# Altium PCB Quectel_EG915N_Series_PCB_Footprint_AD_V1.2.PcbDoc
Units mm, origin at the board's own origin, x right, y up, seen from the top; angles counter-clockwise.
Board outline 152.4 x 101.6 mm, 2 copper layers (Top Layer, Bottom Layer); 1 components, 0 nets, 126 pads, 0 vias.
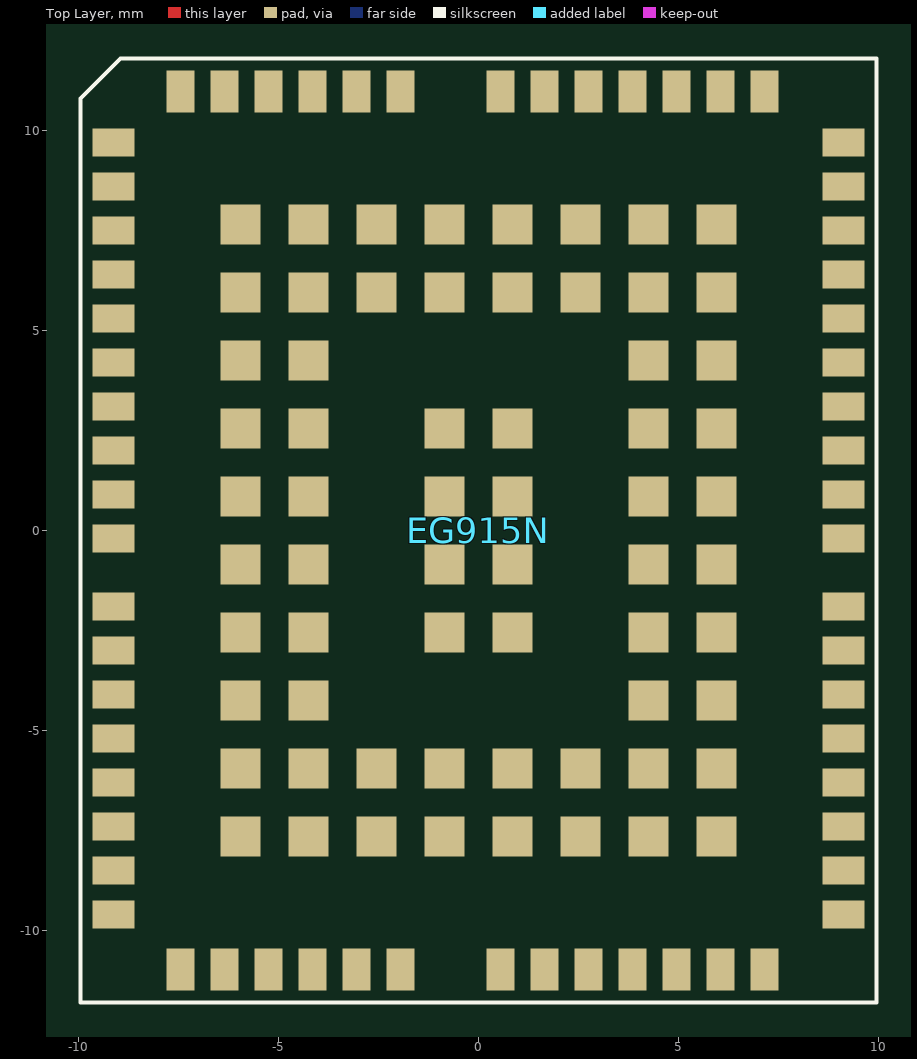
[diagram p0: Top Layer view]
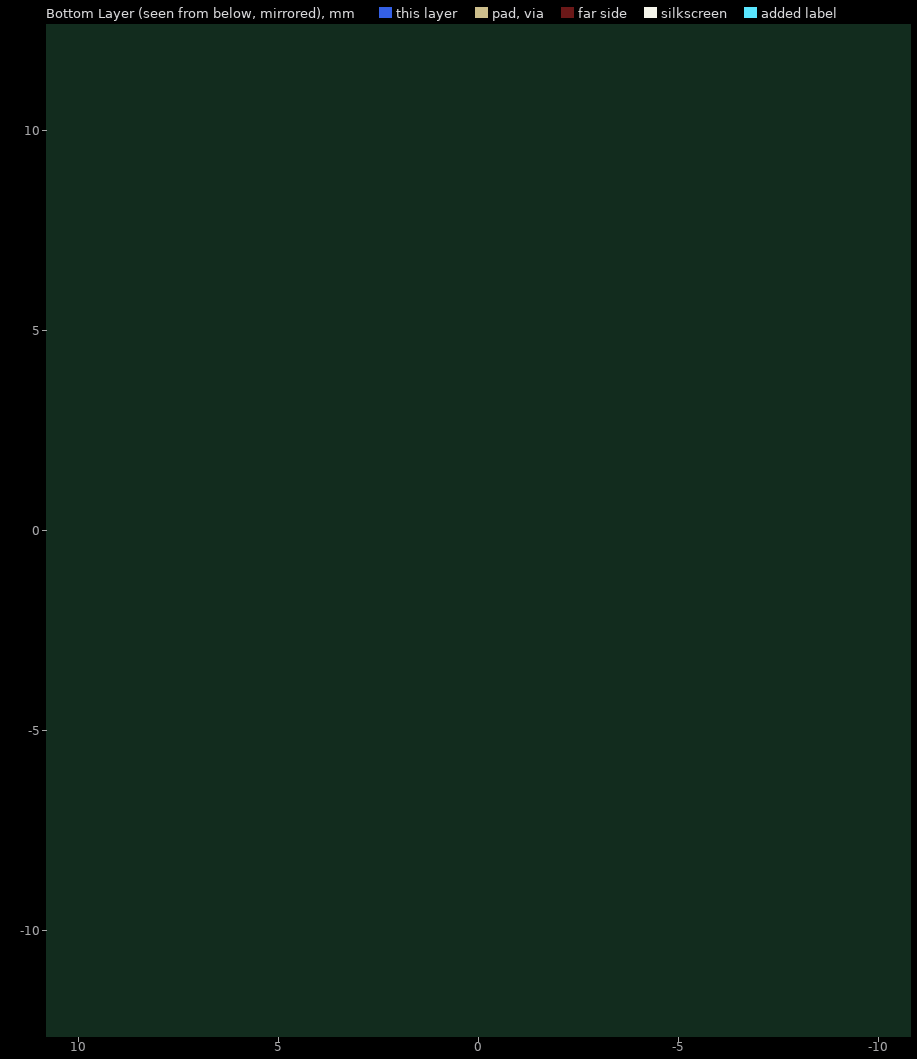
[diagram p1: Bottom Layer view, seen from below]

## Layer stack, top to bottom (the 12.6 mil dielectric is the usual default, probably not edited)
Top Solder: solder mask 0.0102, Solder Resist, Dk 3.5
Top Layer: signal copper 0.0356
Dielectric1: dielectric 0.32, FR-4, Dk 4.8
Bottom Layer: signal copper 0.0356
Bottom Solder: solder mask 0.0102, Solder Resist, Dk 3.5

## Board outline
-70.739,-53.721 81.661,-53.721 81.661,47.879 -70.739,47.879

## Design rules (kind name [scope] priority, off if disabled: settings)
Clearance [All] p1: gap=0.254 ignorepadtopadclearanceinfootprint=FALSE except(0: Arc-Hole Track-Hole SMDPad-Hole THPad-Hole Via-Hole Fill-Hole Poly-Hole Region-Hole Text-Hole)
PolygonConnect [All] p1: connectstyle=Relief reliefconductorwidth=0.254 reliefentries=4 polygonreliefangle="90 Angle" airgapwidth=0.254
RoutingVias [All] p1: holewidth=0.711 width=1.27 viastyle="Through Hole" minholewidth=0.711 minwidth=1.27 maxholewidth=0.711 maxwidth=1.27
SilkToSilkClearance [All] p1 off: silktosilkclearance=0.254
SilkToSolderMaskClearance [IsPad] p1 off: minsilkscreentomaskgap=0.254 clearancetoexposedcopper=TRUE
SolderMaskExpansion [All] p1: expansion=0.102 istentingtop=FALSE
Width [All] p1: maxlimit=0.254 minlimit=0.254 preferedwidth=0.254
28 further rules are at their usual default settings.

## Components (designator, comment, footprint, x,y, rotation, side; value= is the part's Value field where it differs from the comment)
EG915N "Comment" EG915N 0,0 r0 top

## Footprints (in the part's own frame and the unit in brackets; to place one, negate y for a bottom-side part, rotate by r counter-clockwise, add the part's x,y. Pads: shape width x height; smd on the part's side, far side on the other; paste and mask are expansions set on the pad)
EG915N [mm] "EG915N Module LGA126Pin 19.9x23.6mm H2.4mm RO"
  rect 1.05x0.7 smd mask+0.05: 1(-9.125,9.7) 2(-9.125,8.6) 3(-9.125,7.5) 4(-9.125,6.4) 5(-9.125,5.3) 6(-9.125,4.2) 7(-9.125,3.1) 8(-9.125,2) 9(-9.125,0.9) 10(-9.125,-0.2) 11(-9.125,-1.9) 12(-9.125,-3) 13(-9.125,-4.1) 14(-9.125,-5.2) 15(-9.125,-6.3) 16(-9.125,-7.4) 17(-9.125,-8.5) 18(-9.125,-9.6) 32(9.125,-9.6) 33(9.125,-8.5) 34(9.125,-7.4) 35(9.125,-6.3) 36(9.125,-5.2) 37(9.125,-4.1) 38(9.125,-3) 39(9.125,-1.9) 40(9.125,-0.2) 41(9.125,0.9) 42(9.125,2) 43(9.125,3.1) 44(9.125,4.2) 45(9.125,5.3) 46(9.125,6.4) 47(9.125,7.5) 48(9.125,8.6) 49(9.125,9.7)
  rect 0.7x1.05 smd mask+0.05: 19(-7.45,-10.975) 20(-6.35,-10.975) 21(-5.25,-10.975) 22(-4.15,-10.975) 23(-3.05,-10.975) 24(-1.95,-10.975) 25(0.55,-10.975) 26(1.65,-10.975) 27(2.75,-10.975) 28(3.85,-10.975) 29(4.95,-10.975) 30(6.05,-10.975) 31(7.15,-10.975) 50(7.15,10.975) 51(6.05,10.975) 52(4.95,10.975) 53(3.85,10.975) 54(2.75,10.975) 55(1.65,10.975) 56(0.55,10.975) 57(-1.95,10.975) 58(-3.05,10.975) 59(-4.15,10.975) 60(-5.25,10.975) 61(-6.35,10.975) 62(-7.45,10.975)
  rect 1x1 smd mask+0.05: 63(-5.95,4.25) 64(-5.95,2.55) 65(-5.95,0.85) 66(-5.95,-0.85) 67(-5.95,-2.55) 68(-5.95,-4.25) 69(-2.55,-7.65) 70(-0.85,-7.65) 71(0.85,-7.65) 72(2.55,-7.65) 73(5.95,-4.25) 74(5.95,-2.55) 75(5.95,-0.85) 76(5.95,0.85) 77(5.95,2.55) 78(5.95,4.25) 79(2.55,7.65) 80(0.85,7.65) 81(-0.85,7.65) 82(-2.55,7.65) 83(-4.25,4.25) 84(-4.25,2.55) 85(-4.25,0.85) 86(-4.25,-0.85) 87(-4.25,-2.55) 88(-4.25,-4.25) 89(-2.55,-5.95) 90(-0.85,-5.95) 91(0.85,-5.95) 92(2.55,-5.95) 93(4.25,-4.25) 94(4.25,-2.55) 95(4.25,-0.85) 96(4.25,0.85) 97(4.25,2.55) 98(4.25,4.25) 99(2.55,5.95) 100(0.85,5.95) 101(-0.85,5.95) 102(-2.55,5.95) 103(-5.95,7.65) 104(-5.95,5.95) 105(-5.95,-5.95) 106(-5.95,-7.65) 107(-4.25,-7.65) 108(4.25,-7.65) 109(5.95,-7.65) 110(5.95,-5.95) 111(5.95,5.95) 112(5.95,7.65) 113(4.25,7.65) 114(-4.25,7.65) 115(-4.25,5.95) 116(-4.25,-5.95) 117(4.25,-5.95) 118(4.25,5.95) 119(-0.85,2.55) 120(-0.85,0.85) 121(-0.85,-0.85) 122(-0.85,-2.55) 123(0.85,-2.55) 124(0.85,-0.85) 125(0.85,0.85) 126(0.85,2.55)
  silkscreen extent -9.95,-11.8 9.95,11.8, body extent -9.95,-11.8 9.95,11.8, height 2.4

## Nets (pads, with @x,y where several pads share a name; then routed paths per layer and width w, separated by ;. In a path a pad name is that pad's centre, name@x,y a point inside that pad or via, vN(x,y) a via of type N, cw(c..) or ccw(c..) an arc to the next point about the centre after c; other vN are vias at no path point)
pads on no net: EG915N.1 EG915N.2 EG915N.3 EG915N.4 EG915N.5 EG915N.6 EG915N.7 EG915N.8 EG915N.9 EG915N.10 EG915N.11 EG915N.12 EG915N.13 EG915N.14 EG915N.15 EG915N.16 EG915N.17 EG915N.18 EG915N.19 EG915N.20 EG915N.21 EG915N.22 EG915N.23 EG915N.24 EG915N.25 EG915N.26 EG915N.27 EG915N.28 EG915N.29 EG915N.30 EG915N.31 EG915N.32 EG915N.33 EG915N.34 EG915N.35 EG915N.36 EG915N.37 EG915N.38 EG915N.39 EG915N.40 EG915N.41 EG915N.42 EG915N.43 EG915N.44 EG915N.45 EG915N.46 EG915N.47 EG915N.48 EG915N.49 EG915N.50 EG915N.51 EG915N.52 EG915N.53 EG915N.54 EG915N.55 EG915N.56 EG915N.57 EG915N.58 EG915N.59 EG915N.60 EG915N.61 EG915N.62 EG915N.63 EG915N.64 EG915N.65 EG915N.66 EG915N.67 EG915N.68 EG915N.69 EG915N.70 EG915N.71 EG915N.72 EG915N.73 EG915N.74 EG915N.75 EG915N.76 EG915N.77 EG915N.78 EG915N.79 EG915N.80 EG915N.81 EG915N.82 EG915N.83 EG915N.84 EG915N.85 EG915N.86 EG915N.87 EG915N.88 EG915N.89 EG915N.90 EG915N.91 EG915N.92 EG915N.93 EG915N.94 EG915N.95 EG915N.96 EG915N.97 EG915N.98 EG915N.99 EG915N.100 EG915N.101 EG915N.102 EG915N.103 EG915N.104 EG915N.105 EG915N.106 EG915N.107 EG915N.108 EG915N.109 EG915N.110 EG915N.111 EG915N.112 EG915N.113 EG915N.114 EG915N.115 EG915N.116 EG915N.117 EG915N.118 EG915N.119 EG915N.120 EG915N.121 EG915N.122 EG915N.123 EG915N.124 EG915N.125 EG915N.126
